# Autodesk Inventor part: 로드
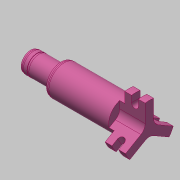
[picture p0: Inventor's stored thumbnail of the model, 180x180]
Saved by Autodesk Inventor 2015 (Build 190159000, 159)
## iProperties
Created: 2020-02
Part Number: 로드
Material: 강철, 연강
Document SubType Name: Modeling
Designer: mduedu
Density: 1 g/cm^3
Appearance: 분홍색
Author: mduedu
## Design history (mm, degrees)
sketch "스케치1"
  geometry: L1 (0, 0)-(-12, 0); L2 (-12, 0)-(-12, 15); L3 (-12, 15)-(0, 15); L4 (0, 15)-(0, 0); L5 (-12, 0)-(-52, 0); L6 (-52, 0)-(-52, 9); L7 (-52, 9)-(-12, 9); L8 (-12, 9)-(-12, 0); L9 (-52, 0)-(-70, 0); L10 (-70, 0)-(-70, 6); L11 (-70, 6)-(-52, 6); L12 (-52, 6)-(-52, 0)
  constraints: 24 end point, 6 parallel, 3 horizontal, 3 perpendicular
  dimensions: "d0" = 70 distance between parallel lines of L4 L10; "d2" = 18 distance of L10.end L11.end; "d3" = 40 distance of L6.end L7.end; "d4" = 12 diameter of L11 L9; "d5" = 18 diameter of L7 L5; "d6" = 30 diameter of L3 L1
revolve "회전1" sketch "스케치1" stored, may be unused: angle "d7" = 90 deg
chamfer "모따기1" distance "d8" = 1.4; stored, may be unused: second distance "d9" = 2, angle "d10" = 15 deg
fillet "모깎기1" dims "d11" = 3
chamfer "모따기2" distance "d12" = 1.4; stored, may be unused: second distance "d13" = 2, angle "d14" = 15 deg
fillet "모깎기2" dims "d15" = 3
sketch "스케치2"
  geometry: L1 (50.981, 8.898)-(52, 8.625) reference; L2 (52, 8.625)-(52, 6) reference; L3 (52, 6)-(68.205, 6) reference; L4 (68.981, 5.898)-(70, 5.625) reference; L5 (70, 5.625)-(70, -5.625) reference; L6 (70, -5.625)-(68.981, -5.898) reference; L7 (68.205, -6)-(52, -6) reference; L8 (52, -6)-(52, -8.625) reference; L9 (52, -8.625)-(50.981, -8.898) reference; L10 (50.205, -9)-(12, -9) reference; L11 (12, -9)-(12, -15) reference; L12 (12, -15)-(0, -15) reference; L13 (0, -15)-(0, 15) reference; L14 (0, 15)-(12, 15) reference; L15 (12, 15)-(12, 9) reference; L16 (12, 9)-(50.205, 9) reference; L17 (0, 0)-(70, 0); L18 (65, 6)-(66.15, 6); L19 (66.15, 6)-(66.15, 5.75); L20 (66.15, 5.75)-(65, 5.75); L21 (65, 5.75)-(65, 6); A1 r 3 centre (50.205, 6) between (50.981, 8.898) and (50.205, 9) reference; A2 r 3 centre (68.205, 3) between (68.981, 5.898) and (68.205, 6) reference; A3 r 3 centre (68.205, -3) between (68.205, -6) and (68.981, -5.898) reference; A4 r 3 centre (50.205, -6) between (50.205, -9) and (50.981, -8.898) reference
  constraints: 10 end point, 2 parallel, 1 horizontal, 1 midpoint, 1 perpendicular, 1 point on line
  dimensions: "d16" = 13 distance between parallel lines of L21 L2; "d17" = 1.15 distance of L18.start L18.end; "d18" = 11.5 diameter of L20 L17
revolve "회전2" sketch "스케치2" stored, may be unused: angle "d19" = 90 deg
sketch "스케치3"
  geometry: L1 (0, 0)-(-15, 0); L2 (0, 0)-(7.5, -12.99); L3 (0, 0)-(7.5, 12.99); L4 (-1.443, -2.5)-(-14.79, -2.5); L5 (-1.443, 2.5)-(-14.79, 2.5); L6 (-1.443, -2.5)-(5.23, -14.059); L7 (2.887, 0)-(9.56, -11.559); L8 (2.887, 0)-(9.56, 11.559); L9 (-1.443, 2.5)-(5.23, 14.059); C1 r 15 at (0, 0) reference; 1 further point
  constraints: 18 end point, 6 parallel, 1 coincident, 1 horizontal, 15 other
  dimensions: "d20" = 120 deg angle of L2 L1; "d21" = 120 deg angle of L3 L1; "d22" = 5 distance between parallel lines of L5 L4; "d24" = 5 distance between parallel lines of L7 L6; "d25" = 5 distance between parallel lines of L9 L8
extrude "돌출1" cut sketch "스케치3" distance "d26" = 15; taper "d27" = 0 deg
fillet "모깎기3" dims "d28" = 5
sketch "스케치4"
  geometry: L1 (4, 21)-(8, 21); L2 (8, 21)-(8, 11); L3 (8, 11)-(4, 11); L4 (4, 11)-(4, 21); 2 further points
  constraints: 8 end point, 2 parallel, 1 horizontal, 1 horizontal alignment, 1 midpoint, 1 perpendicular, 2 other
  dimensions: "d29" = 11 distance from line of L3 point (0, 0); "d30" = 4 distance of L1.start L1.end; "d31" = 6 horizontal distance of point (6, 11) point (0, 0); "d32" = 10 distance between parallel lines of L1 L3
extrude "돌출2" cut sketch "스케치4" stored distance "d33" = 15; taper "d34" = 0 deg
node "솔리드1"
pattern_circular "원형 패턴1" dims angle "d36" = 360 deg
node "투영된 루프1"
node "절단 모서리 투영1"
